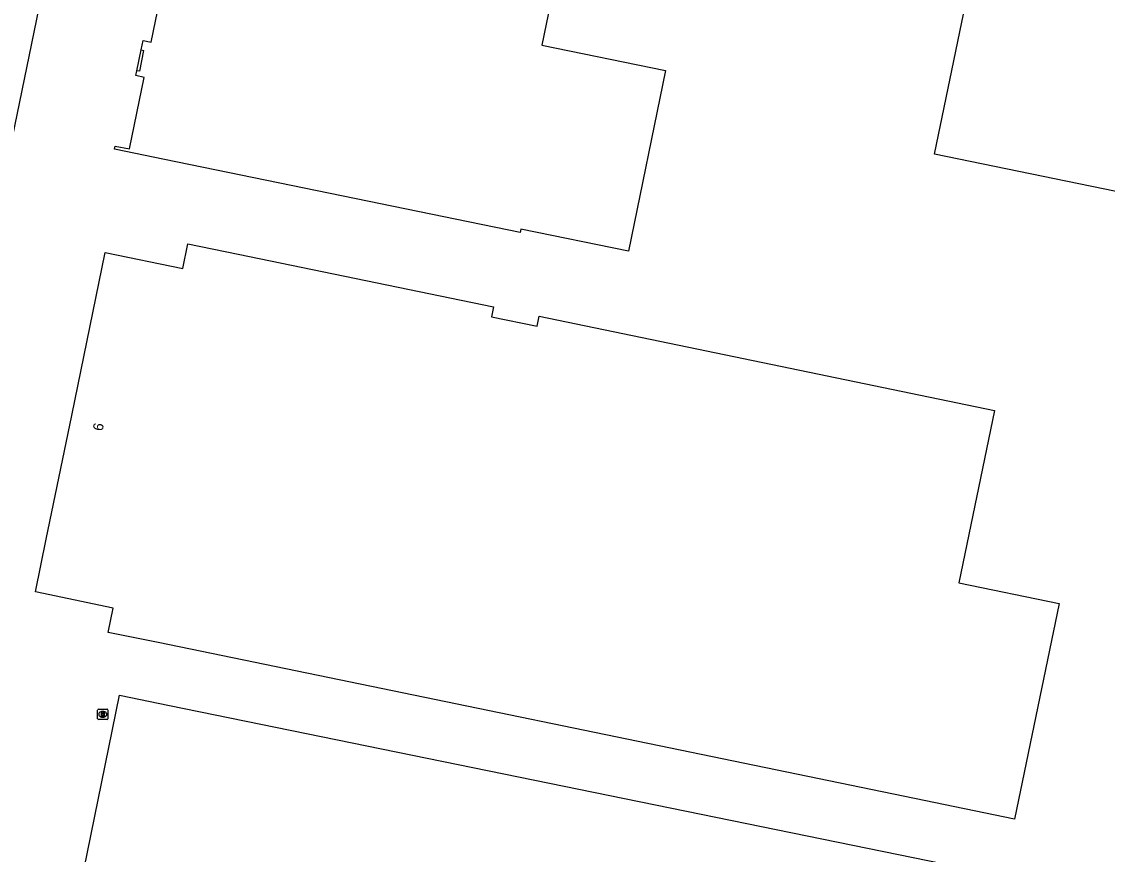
# Model space of a CAD drawing. Extents: x 157692 to 159670, y 381454 to 383289.
# Drawn here: x 158259.4 to 158365.6, y 382338.8 to 382420.3 of the extents above; entities that cross this region are included whole.
import ezdxf

# ---------------------------------------------------------------- set-up
doc = ezdxf.new("R2010")
doc.units = 0
for name, color, linetype in [('IMGEO_Erf', 7, 'Continuous'), ('IMGEO_Pand', 7, 'Continuous'), ('IMGEO_Pand_nummerreeks', 7, 'Continuous'), ('IMGEO_Rioolput', 7, 'Continuous'), ('IMGEO_Voetpad_open', 7, 'Continuous')]:
    doc.layers.add(name, color=color, linetype=linetype)

msp = doc.modelspace()

# ---------------------------------------------------------------- linework, layer by layer
at = {"layer": 'IMGEO_Erf'}
msp.add_lwpolyline([(158270.67, 382415.46), (158271.09, 382417.49)], dxfattribs=at)
at = {"layer": 'IMGEO_Pand'}
for points in [[(158348.75, 382407.31), (158352.91, 382427.48), (158352.81, 382427.5), (158355.15, 382438.89), (158355.26, 382438.88), (158359.39, 382458.96), (158368.21, 382457.15)], [(158271.09, 382417.49), (158271.28, 382418.42), (158272.08, 382418.25), (158277.31, 382443.57), (158277.71, 382443.49), (158277.64, 382443.12), (158280.99, 382442.44), (158282.54, 382442.12), (158315.53, 382435.38), (158315.46, 382435.06), (158313.89, 382435.38), (158310.32, 382417.96), (158322.41, 382415.48), (158318.78, 382397.81), (158308.26, 382399.97), (158308.2, 382399.64), (158273.39, 382406.77), (158268.49, 382407.77), (158268.57, 382408.09), (158269.97, 382407.8), (158271.38, 382414.81), (158270.57, 382414.99), (158270.67, 382415.46)], [(158271.09, 382417.49), (158271.34, 382417.43), (158270.92, 382415.41), (158270.67, 382415.46)], [(158379.37, 382401), (158348.75, 382407.31)], [(158356.58, 382342.22), (158346.79, 382344.24), (158272.77, 382359.5), (158267.87, 382360.51), (158268.36, 382362.88), (158260.75, 382364.48), (158261.81, 382369.61), (158264.3, 382381.73), (158267.57, 382397.67), (158275.17, 382396.12), (158275.68, 382398.52), (158280.58, 382397.51), (158305.58, 382392.35), (158305.38, 382391.37), (158309.84, 382390.45), (158310.05, 382391.43), (158354.61, 382382.23), (158351.13, 382365.34), (158360.93, 382363.33), (158356.58, 382342.22)], [(158255.36, 382287.79), (158268.98, 382354.35), (158273.88, 382353.35), (158404.58, 382326.64)]]:
    msp.add_lwpolyline(points, dxfattribs=at)
at = {"layer": 'IMGEO_Rioolput'}
for p, q in [((158266.84, 382352.06), (158266.84, 382352.91)), ((158266.92, 382352.99), (158267.77, 382352.99)), ((158267.33, 382352.77), (158267.36, 382352.77)), ((158267.84, 382352.91), (158267.84, 382352.06)), ((158267.77, 382351.99), (158266.92, 382351.99)), ((158267.35, 382352.21), (158267.33, 382352.21))]:
    msp.add_line(p, q, dxfattribs=at)
for points in [[(158266.84, 382352.06), (158266.84, 382352.91)], [(158266.92, 382352.99), (158267.77, 382352.99)], [(158267.84, 382352.91), (158267.84, 382352.06)], [(158267.77, 382351.99), (158266.92, 382351.99)], [(158267.43, 382352.69), (158267.18, 382352.69), (158267.18, 382352.29)], [(158267.18, 382352.29), (158267.3, 382352.29), (158267.3, 382352.45), (158267.31, 382352.45)], [(158267.36, 382352.61), (158267.3, 382352.61), (158267.3, 382352.53)], [(158267.3, 382352.53), (158267.35, 382352.53)], [(158267.36, 382352.42), (158267.43, 382352.29), (158267.57, 382352.29), (158267.51, 382352.41)]]:
    msp.add_lwpolyline(points, dxfattribs=at)
for centre, radius, start, end in [((158266.92, 382352.91), 0.0765, 91.552, 178.448), ((158266.92, 382352.91), 0.0765, 91.552, 178.448), ((158267.77, 382352.91), 0.0765, 1.552, 88.448), ((158267.77, 382352.91), 0.0765, 1.552, 88.448), ((158266.92, 382352.06), 0.0765, 181.552, 268.448), ((158266.92, 382352.06), 0.0765, 181.552, 268.448), ((158267.31, 382352.4), 0.0533, 26.0293, 88.6989), ((158267.34, 382352.72), 0.19, 274.7715, 282.9687), ((158267.36, 382352.51), 0.0964, 77.0061, 93.1865), ((158267.38, 382352.57), 0.0378, 276.6634, 79.6772), ((158267.43, 382352.58), 0.109, 350.3612, 89.416), ((158267.43, 382352.58), 0.112, 277.5842, 350.9817), ((158267.41, 382352.36), 0.108, 29.5134, 73.7905), ((158267.77, 382352.06), 0.0765, 271.552, 358.448), ((158267.77, 382352.06), 0.0765, 271.552, 358.448)]:
    msp.add_arc(centre, radius, start, end, dxfattribs=at)
for centre, major_axis, ratio, start_param, end_param in [((158267.33, 382352.49), (-0.387, 0.002), 0.722429, 4.712389, 7.853982), ((158267.35, 382352.49), (-0.39, 0.002), 0.717154, 1.570796, 4.712389)]:
    msp.add_ellipse(centre, major_axis=major_axis, ratio=ratio, start_param=start_param, end_param=end_param, dxfattribs=at)
at = {"layer": 'IMGEO_Voetpad_open'}
msp.add_lwpolyline([(158282.25, 382524.53), (158280.6, 382516.58), (158277.15, 382500), (158276.98, 382499.14), (158273.83, 382483.72), (158267, 382450.35), (158258.47, 382408.94), (158257.07, 382402.08), (158248.21, 382358.84), (158244.45, 382340.75)], dxfattribs=at)

# ---------------------------------------------------------------- texts
at = {"layer": 'IMGEO_Pand_nummerreeks'}
msp.add_text('6', height=1, rotation=78.3896, dxfattribs=at).set_placement((158267.32, 382380.15))

doc.saveas('drawing.dxf')
